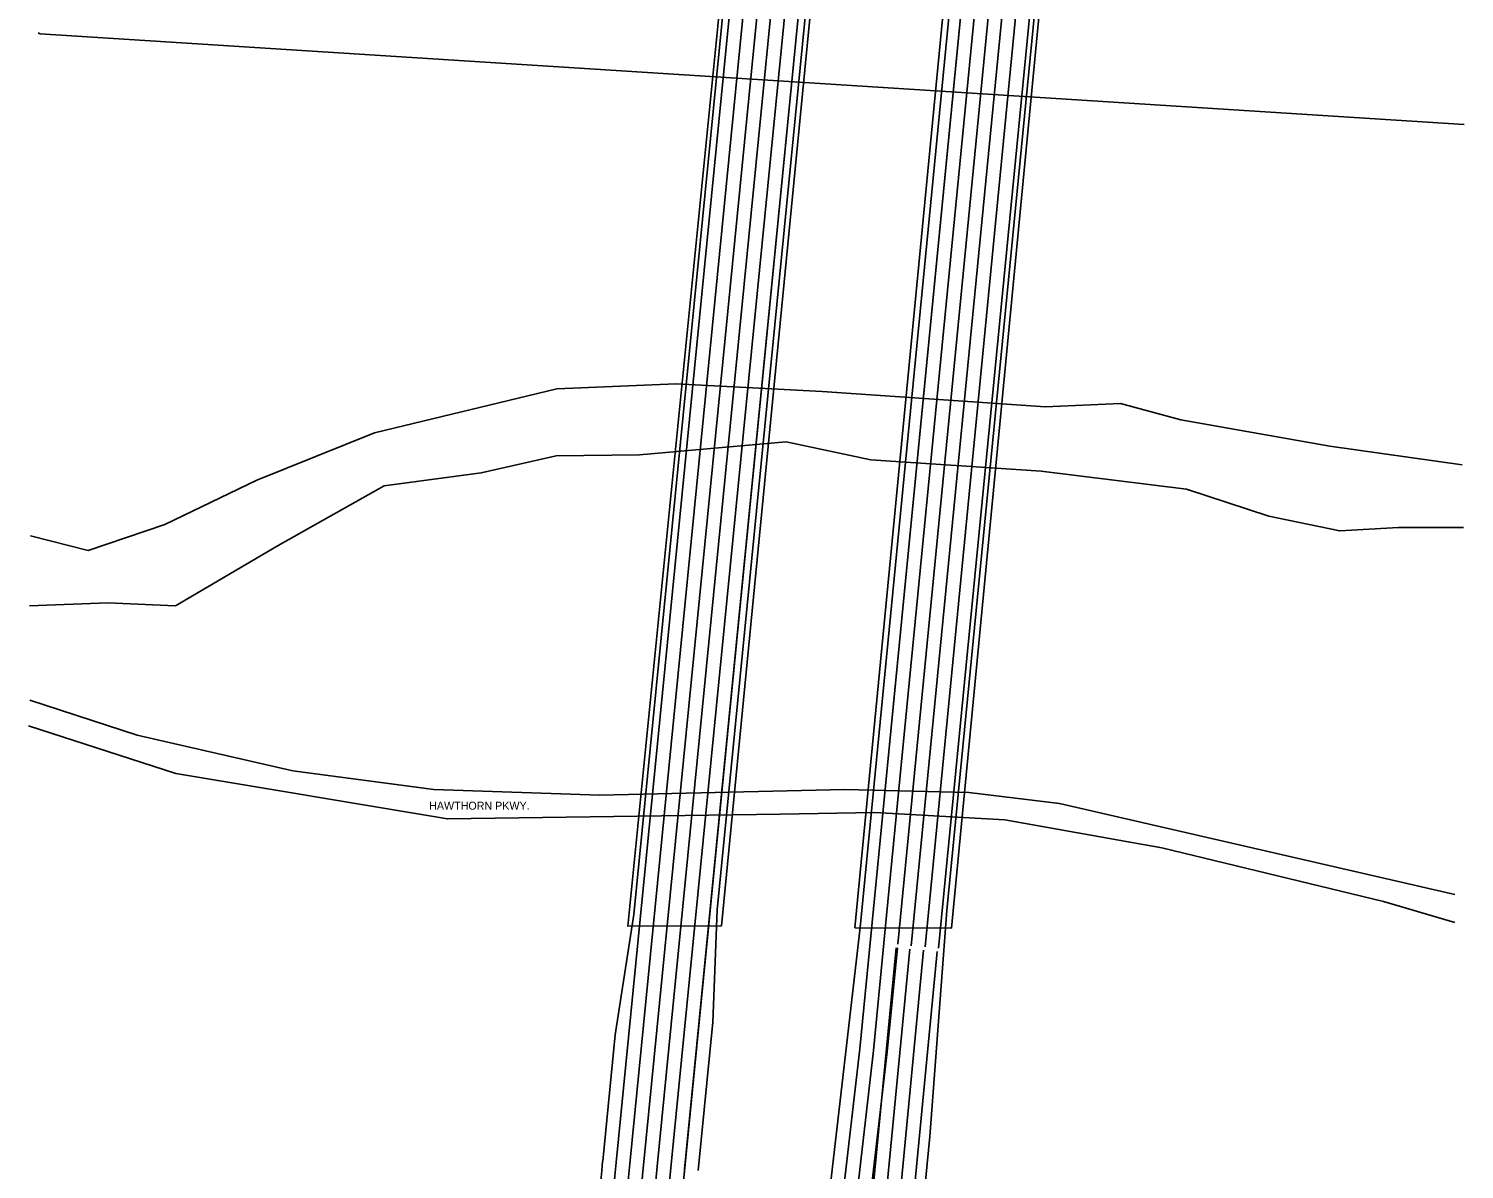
# Model space of a CAD drawing. Extents: x 227157 to 233208, y 434992 to 456232.
# Drawn here: x 228490 to 229745, y 449096 to 450094 of the extents above; entities that cross this region are included whole.
import ezdxf

# ---------------------------------------------------------------- set-up
doc = ezdxf.new("R2010")
doc.units = 0
for name, color, linetype in [('BR_X_Slab_Object', 7, 'Continuous'), ('GE_X_Alignment', 7, 'Continuous'), ('HY_X_Water_Edge', 7, 'Continuous'), ('PM_X_Edge_Line', 7, 'Continuous'), ('PM_X_Lane_Line', 7, 'Continuous'), ('PV_X_EOP', 7, 'Continuous'), ('RD_X_RR_1', 7, 'Continuous'), ('SV_X_Text_Name', 7, 'Continuous')]:
    doc.layers.add(name, color=color, linetype=linetype)

msp = doc.modelspace()

# ---------------------------------------------------------------- linework, layer by layer
at = {"layer": 'BR_X_Slab_Object'}
for points in [[(229212.1, 449307.6), (229296.9, 449307.3), (229404.3, 450429.2), (229319.1, 450416.6)], [(229095.5, 449309.3), (229013.6, 449309), (229121.5, 450387.8), (229201.6, 450399.2)]]:
    msp.add_lwpolyline(points, close=True, dxfattribs=at)
at = {"layer": 'GE_X_Alignment'}
for p, q in [((229216.7, 449201.7), (229389.5, 450973.9)), ((228999.7, 448451.5), (229245, 450938.7)), ((228965.9, 446344.9), (229248.4, 449290.1)), ((229216.7, 449201.7), (228846.5, 446019.3))]:
    msp.add_line(p, q, dxfattribs=at)
at = {"layer": 'HY_X_Water_Edge'}
for points in [[(228491.1, 449650.3), (228541.7, 449637.5), (228608.7, 449660.3), (228689.3, 449698.9), (228792, 449740.2), (228951.7, 449778.8), (229055.9, 449783.1), (229183.5, 449776.6), (229378.9, 449763.1), (229444.5, 449765.9), (229497.3, 449751.7), (229627.8, 449728.8), (229743.3, 449712.4)], [(228490.4, 449589), (228558.8, 449591.8), (228618, 449589), (228707.9, 449641.8), (228800.6, 449693.9), (228885.4, 449705.3), (228951, 449720.3), (229023.8, 449721), (229152.1, 449732.4), (229226.3, 449716.7), (229375.3, 449706.7), (229502.3, 449691), (229574.3, 449667.5), (229636.3, 449654.6), (229687.7, 449657.5), (229744.7, 449657.5)]]:
    msp.add_lwpolyline(points, dxfattribs=at)
at = {"layer": 'PM_X_Edge_Line'}
for p, q in [((229148.5, 450571.9), (229003.6, 449102.3)), ((229063.3, 449096.4), (229208.2, 450566)), ((229216.7, 449201.7), (229345.9, 450527.2)), ((229285.5, 449289.8), (229405.6, 450521.4)), ((229027.5, 449099.9), (229092.7, 449761)), ((229071.9, 447449.9), (229248.4, 449290.1)), ((229161.5, 448007.4), (229284.2, 449286.7)), ((229240.5, 449199.1), (229249.4, 449289.9)), ((229004.6, 447378.9), (229216.7, 449201.7)), ((229028.5, 447376.1), (229240.5, 449199.1))]:
    msp.add_line(p, q, dxfattribs=at)
for radius, end in [(11246, 175.31246), (11222, 175.06141)]:
    msp.add_arc((240195.3, 447998.8), radius, 174.36867, end, dxfattribs=at)
at = {"layer": 'PM_X_Lane_Line'}
for p, q in [((229160.4, 450570.7), (229015.5, 449101.1)), ((229039.4, 449098.8), (229184.3, 450568.3)), ((229196.3, 450567.2), (229051.4, 449097.6)), ((229092.7, 449761), (229172.4, 450569.5)), ((229237.7, 449294.3), (229357.9, 450526.1)), ((229249.7, 449293.1), (229369.8, 450524.9)), ((229261.6, 449291.9), (229381.7, 450523.7)), ((229273.6, 449290.8), (229393.7, 450522.6)), ((229237.7, 449294), (229228.6, 449200.4)), ((229083.8, 447448.8), (229260.3, 449289)), ((229095.8, 447447.6), (229272.3, 449287.9)), ((229228.6, 449200.4), (229016.5, 447377.5))]:
    msp.add_line(p, q, dxfattribs=at)
for radius, end in [(11210, 177.45228), (11234, 175.31246), (11198, 177.45228)]:
    msp.add_arc((240195.3, 447998.8), radius, 174.36867, end, dxfattribs=at)
at = {"layer": 'PV_X_EOP'}
for p, q in [((229091.7, 449323.4), (229209.7, 450519.5)), ((229292.8, 449322.7), (229407.8, 450502.2)), ((229216.9, 449307.7), (229328.9, 450455.6)), ((229019, 449319.3), (229127.6, 450421)), ((229002.5, 449213.9), (229019, 449319.3)), ((229088, 449225), (229091.7, 449323.4)), ((229277.8, 449125.2), (229292.8, 449322.7)), ((229185.2, 449035.2), (229216.9, 449307.7)), ((229075.2, 449095.2), (229088, 449225)), ((228991.7, 449103.5), (229002.5, 449213.9)), ((229170.5, 448006.5), (229277.8, 449125.2))]:
    msp.add_line(p, q, dxfattribs=at)
for points in [[(229736.9, 449336.6), (229391.3, 449416.1), (229311.9, 449425.9), (229203.5, 449428.4), (228989.2, 449423.5), (228844.1, 449428.4), (228720.7, 449444.7), (228584.6, 449476.1), (228490.5, 449506.6)], [(228489.6, 449484.2), (228618.4, 449442.6), (228855.9, 449402.7), (229146.9, 449406.8), (229229.6, 449408.4), (229343.3, 449401.9), (229480.6, 449377.4), (229674.5, 449330.5), (229736.9, 449312.2)]]:
    msp.add_lwpolyline(points, dxfattribs=at)
msp.add_arc((240195.3, 447998.8), 11258, 174.36867, 175.072, dxfattribs=at)
at = {"layer": 'RD_X_RR_1'}
msp.add_lwpolyline([(228498, 450090.2), (228499.6, 450089.3), (229745.3, 450009.8)], dxfattribs=at)

# ---------------------------------------------------------------- texts
at = {"layer": 'SV_X_Text_Name'}
msp.add_text('HAWTHORN PKWY.', height=7, dxfattribs=at).set_placement((228839.9, 449410.8))

doc.saveas('drawing.dxf')
